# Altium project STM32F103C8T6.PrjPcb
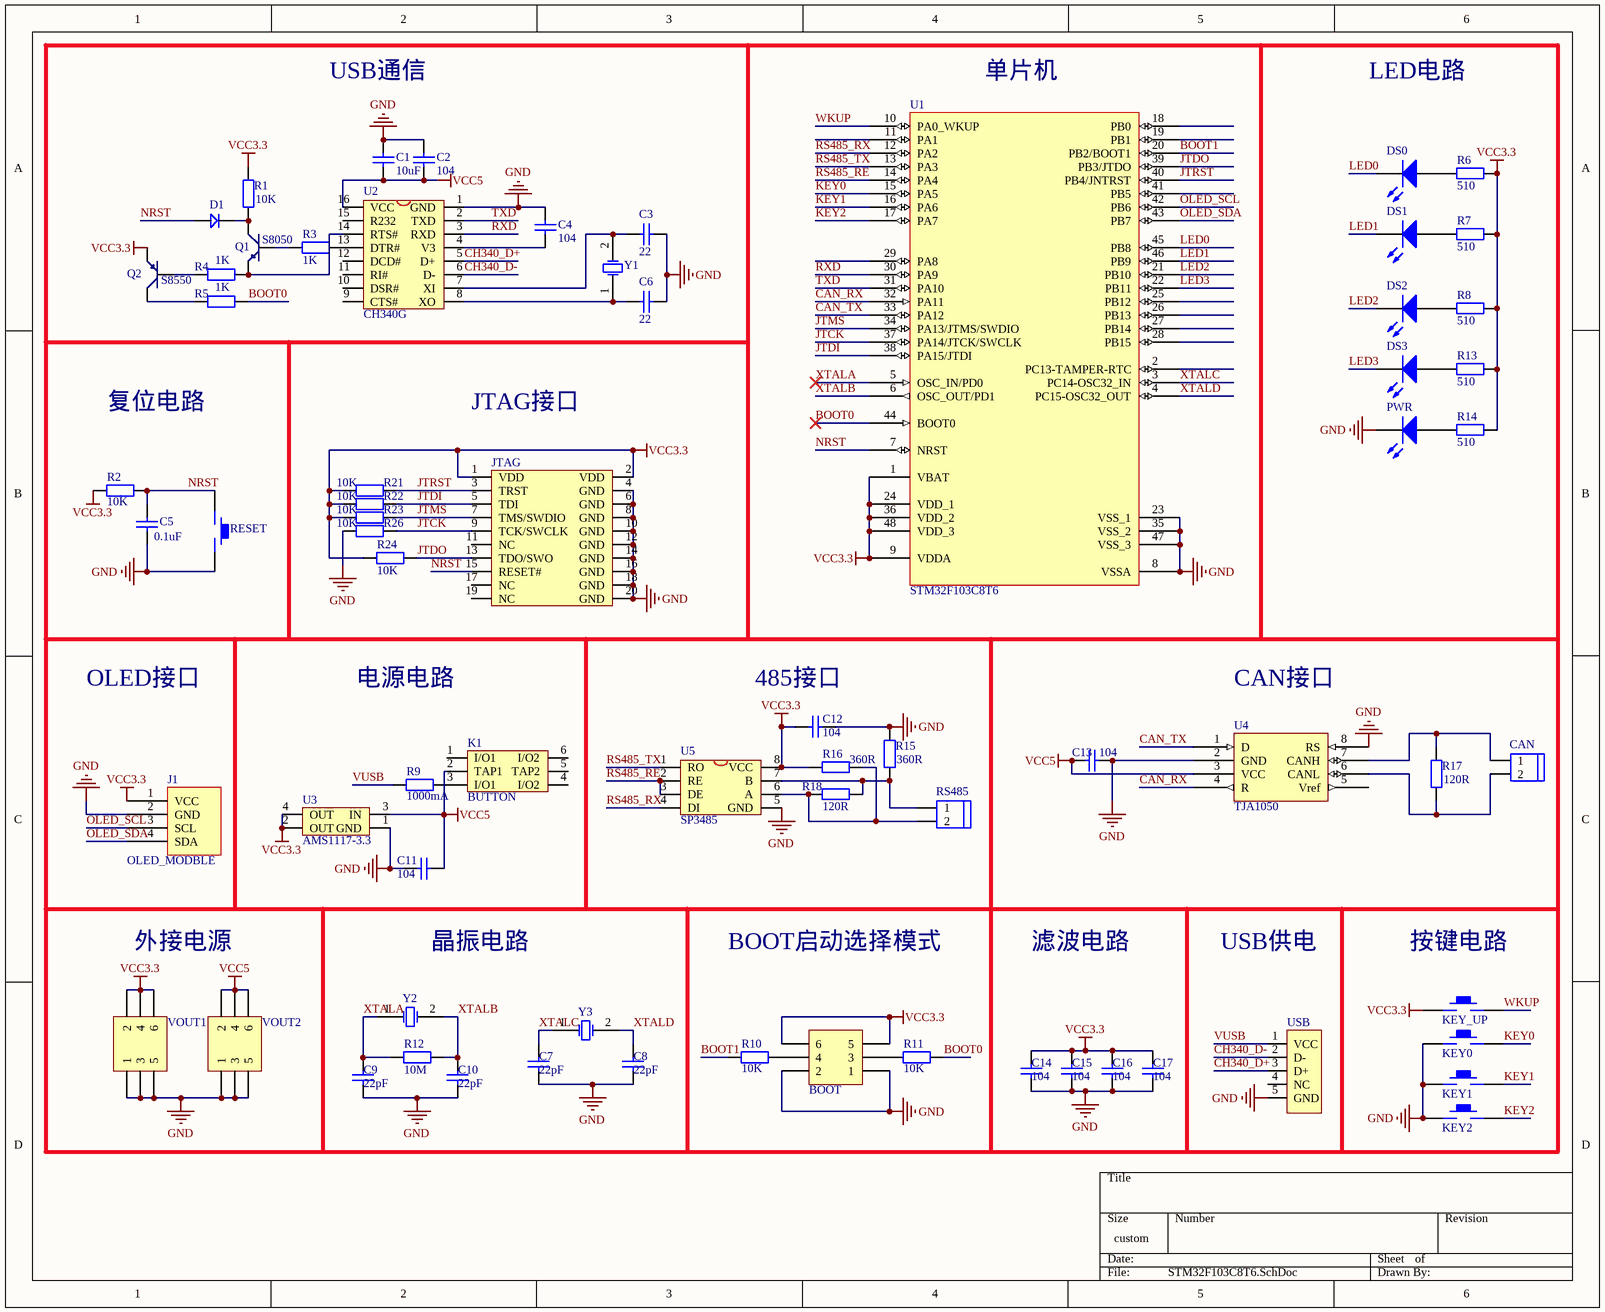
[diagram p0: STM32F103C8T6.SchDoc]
1 sheet, 70 parts. Net scope: global (net labels, ports and power ports of the same name join across sheets).
Board file: STM32F103C8T6.PcbDoc

## Sheet STM32F103C8T6.SchDoc
size 299 x 245 mm

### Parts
BOOT  Header 3X2  [HDR2X3]  (value not drawn)
C1  value 10uF  [0805]  (hidden comment: Cap)
C2  value 104  [0805]  (hidden comment: Cap)
C3  value 22  [0805]  (hidden comment: Cap)
C4  value 104  [0805]  (hidden comment: Cap)
C5  value 0.1uF  [0805]  (hidden comment: Cap)
C6  value 22  [0805]  (hidden comment: Cap)
C7  value 22pF  [0805]  (hidden comment: Cap)
C8  value 22pF  [0805]  (hidden comment: Cap)
C9  value 22pF  [0805]  (hidden comment: Cap)
C10  value 22pF  [0805]  (hidden comment: Cap)
C11  value 104  [0805]  (hidden comment: Cap)
C12  value 104  [0805]  (hidden comment: Cap)
C13  value 104  [0805]  (hidden comment: Cap)
C14  value 104  [0805]  (hidden comment: Cap)
C15  value 104  [0805]  (hidden comment: Cap)
C16  value 104  [0805]  (hidden comment: Cap)
C17  value 104  [0805]  (hidden comment: Cap)
CAN  CAN  [HEAD2L-0.8]  (value not drawn)
D1  1N4148  [DIODE_SOP]  (value not drawn)
DS0  LED1  [SMDLED]  (value not drawn)
DS1  LED1  [SMDLED]  (value not drawn)
DS2  LED1  [SMDLED]  (value not drawn)
DS3  LED1  [SMDLED]  (value not drawn)
J1  OLED_MODBLE  [HEAD4]
JTAG  JTAG  [JTAG_20]  (value not drawn)
K1  BUTTON  [BTN8.5*8.5]
KEY0  KEY_M  [KEY_M]  (value not drawn)
KEY1  KEY_M  [KEY_M]  (value not drawn)
KEY2  KEY_M  [KEY_M]  (value not drawn)
KEY_UP  KEY_M  [KEY_M]  (value not drawn)
PWR  LED1  [SMDLED]  (value not drawn)
Q1  S8050  [SOT-23R]
Q2  S8550  [SOT-23R]
R1  value 10K  [R0805]  (hidden comment: Res2)
R2  value 10K  [R0805]  (hidden comment: Res2)
R3  value 1K  [R0805]  (hidden comment: Res2)
R4  value 1K  [R0805]  (hidden comment: Res2)
R5  value 1K  [R0805]  (hidden comment: Res2)
R6  value 510  [R0805]  (hidden comment: Res2)
R7  value 510  [R0805]  (hidden comment: Res2)
R8  value 510  [R0805]  (hidden comment: Res2)
R9  value 1000mA  [R0805]  (hidden comment: Res2)
R10  value 10K  [R0805]  (hidden comment: Res2)
R11  value 10K  [R0805]  (hidden comment: Res2)
R12  value 10M  [R0805]  (hidden comment: Res2)
R13  value 510  [R0805]  (hidden comment: Res2)
R14  value 510  [R0805]  (hidden comment: Res2)
R15  value 360R  [R0805]  (hidden comment: Res2)
R16  value 360R  [R0805]  (hidden comment: Res2)
R17  value 120R  [R0805]  (hidden comment: Res2)
R18  value 120R  [R0805]  (hidden comment: Res2)
R21  value 10K  [R0805]  (hidden comment: Res2)
R22  value 10K  [R0805]  (hidden comment: Res2)
R23  value 10K  [R0805]  (hidden comment: Res2)
R24  value 10K  [R0805]  (hidden comment: Res2)
R26  value 10K  [R0805]  (hidden comment: Res2)
RESET  KEY_M  [KEY_M]  (value not drawn)
RS485  RS485  [HEAD2L-0.8]  (value not drawn)
U1  STM32F103C8T6  [LQFP48_N]
U2  CH340G  [SOP16M]
U3  AMS1117-3.3  [AMS1117]
U4  TJA1050  [SOP-8]
U5  SP3485  [SOP-8]
USB  USB  [USB/SM0.8-6H5]  (value not drawn)
VOUT1  Header 3X2  [HDR2X3]  (value not drawn)
VOUT2  Header 3X2  [HDR2X3]  (value not drawn)
Y1  8M  [XTAL_US]  (value not drawn)
Y2  8M  [XTAL_US]  (value not drawn)
Y3  32.768k  [32.768K晶振]  (value not drawn)

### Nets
GND: BOOT.1 BOOT.2 C1.1 C2.1 C3.1 C4.2 C5.1 C6.1 C7.1 C8.1 C9.1 C10.1 C11.1 C12.2 C13.1 C14.1 C15.1 C16.1 C17.1 J1.2(GND) JTAG.4(GND) JTAG.6(GND) JTAG.8(GND) JTAG.10(GND) JTAG.12(GND) JTAG.14(GND) JTAG.16(GND) JTAG.18(GND) JTAG.20(GND) KEY0.1 KEY1.1 KEY2.1 PWR.2(K) R15.2 R26.1 RESET.2 U1.8(VSSA) U1.23(VSS_1) U1.35(VSS_2) U1.47(VSS_3) U2.1(GND) U3.1(GND) U4.2(GND) U4.8(RS) U5.5(GND) USB.5(GND) VOUT1.1 VOUT1.3 VOUT1.5 VOUT2.1 VOUT2.3 VOUT2.5
VCC3.3: BOOT.5 BOOT.6 C12.1 C14.2 C15.2 C16.2 C17.2 J1.1(VCC) JTAG.1(VDD) JTAG.2(VDD) KEY_UP.1 Q2.1(E) R1.2 R2.2 R6.1 R7.1 R8.1 R13.1 R14.1 R16.1 R21.2 R22.2 R23.2 R24.1 U1.1(VBAT) U1.9(VDDA) U1.24(VDD_1) U1.36(VDD_2) U1.48(VDD_3) U3.2(OUT) U3.4(OUT) U5.8(VCC) VOUT1.2 VOUT1.4 VOUT1.6
VCC5: C1.2 C2.2 C11.2 C13.2 K1.2(TAP1) U2.16(VCC) U3.3(IN) U4.3(VCC) VOUT2.2 VOUT2.4 VOUT2.6
BOOT0: R5.2 R11.1 U1.44(BOOT0)
BOOT1: R10.2 U1.20(PB2/BOOT1)
CAN_RX: U1.32(PA11) U4.4(R)
CAN_TX: U1.33(PA12) U4.1(D)
CH340_D+: U2.5(D+) USB.3(D+)
CH340_D-: U2.6(D-) USB.2(D-)
JTCK: JTAG.9(TCK/SWCLK) R26.2 U1.37(PA14/JTCK/SWCLK)
JTDI: JTAG.5(TDI) R22.1 U1.38(PA15/JTDI)
JTDO: JTAG.13(TDO/SWO) R24.2 U1.39(PB3/JTDO)
JTMS: JTAG.7(TMS/SWDIO) R23.1 U1.34(PA13/JTMS/SWDIO)
JTRST: JTAG.3(TRST) R21.1 U1.40(PB4/JNTRST)
KEY0: KEY0.2 U1.15(PA5)
KEY1: KEY1.2 U1.16(PA6)
KEY2: KEY2.2 U1.17(PA7)
LED0: DS0.2(K) U1.45(PB8)
LED1: DS1.2(K) U1.46(PB9)
LED2: DS2.2(K) U1.21(PB10)
LED3: DS3.2(K) U1.22(PB11)
NRST: C5.2 D1.1 JTAG.15(RESET#) R2.1 RESET.1 U1.7(NRST)
OLED_SCL: J1.3(SCL) U1.42(PB6)
OLED_SDA: J1.4(SDA) U1.43(PB7)
RS485_RE: U1.14(PA4) U5.2(RE) U5.3(DE)
RS485_RX: U1.12(PA2) U5.4(DI)
RS485_TX: U1.13(PA3) U5.1(RO)
RXD: U1.30(PA9) U2.3(RXD)
TXD: U1.31(PA10) U2.2(TXD)
VUSB: R9.2 USB.1(VCC)
WKUP: KEY_UP.2 U1.10(PA0_WKUP)
XTALA: C9.2 R12.2 U1.5(OSC_IN/PD0) Y2.1(OSC1)
XTALB: C10.2 R12.1 U1.6(OSC_OUT/PD1) Y2.2(OSC2)
XTALC: C7.2 U1.3(PC14-OSC32_IN) Y3.1(OSC1)
XTALD: C8.2 U1.4(PC15-OSC32_OUT) Y3.2(OSC2)
NetBOOT_3: BOOT.3 R11.2
NetBOOT_4: BOOT.4 R10.1
NetC3_2: C3.2 U2.7(XI) Y1.2(OSC2)
NetC4_1: C4.1 U2.4(V3)
NetC6_2: C6.2 U2.8(XO) Y1.1(OSC1)
NetCAN_1: CAN.1 R17.2 U4.7(CANH)
NetCAN_2: CAN.2 R17.1 U4.6(CANL)
NetD1_2: D1.2 Q1.3(C) R1.1
NetDS0_1: DS0.1(A) R6.2
NetDS1_1: DS1.1(A) R7.2
NetDS2_1: DS2.1(A) R8.2
NetDS3_1: DS3.1(A) R13.2
NetK1_3: K1.3(I/O1) R9.1
NetPWR_1: PWR.1(A) R14.2
NetQ1_1: Q1.1(E) R4.2 U2.14(RTS#)
NetQ1_2: Q1.2(B) R3.1
NetQ2_2: Q2.2(B) R4.1
NetQ2_3: Q2.3(C) R5.1
NetR3_2: R3.2 U2.13(DTR#)
NetR15_1: R15.1 R18.2 RS485.1 U5.7(B)
NetR16_2: R16.2 R18.1 RS485.2 U5.6(A)

Not connected (* = marked no-connect by the designer): JTAG 11(NC) 17(NC) 19(NC); K1 1(I/O1) 4(I/O2) 5(TAP2) 6(I/O2); U1 2(PC13-TAMPER-RTC) 11(PA1) 18(PB0) 19(PB1) 25(PB12) 26(PB13) 27(PB14) 28(PB15) 29(PA8) 41(PB5); U2 9(CTS#) 10(DSR#) 11(RI#) 12(DCD#) 15(R232); U4 5(Vref); USB 4(NC)

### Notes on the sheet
- USB通信
- (near U1) 单片机
- LED电路
- 复位电路
- JTAG接口
- OLED接口
- 电源电路
- (near C12) 485接口
- CAN接口
- 外接电源
- 晶振电路
- BOOT启动选择模式
- 滤波电路
- USB供电
- 按键电路

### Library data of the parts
BOOT VOUT1 VOUT2 = Header 3X2: Header, 3-Pin, Dual row
C1-C17 = Cap: Capacitor
CAN RS485 = HEAD2
D1 = D
DS0-DS3 PWR = LED2: Typical RED, GREEN, YELLOW, AMBER GaAs LED
Q1 = NPN: 8050/BCW846/BCW847
Q2 = PNP: 8550/BCW68
R1-R18 R21-R24 R26 = Res2: Resistor
U2 = CH340G: USB2UART
U3 = AMS1117
U4 = SN65HVD230D
U5 = MAX3485
USB = USB5
Y1-Y3 = XTAL: Crystal Oscillator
